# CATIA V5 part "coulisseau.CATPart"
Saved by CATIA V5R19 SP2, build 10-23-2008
Part number: coulisseau
Bounding box of the stored display mesh (mm): x 0 to 20, y -15 to 15, z -15 to 15
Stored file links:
  F:\iaoifma\coulisseau.CATPart
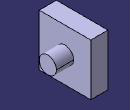
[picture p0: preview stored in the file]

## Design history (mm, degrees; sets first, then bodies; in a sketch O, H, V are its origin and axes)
Body1 (main body)
  Sketch1 on yz-plane, origin (0, 0, 0), H (0, 1, 0), V (0, 0, 1)
    line L1 (-15, 15) -> (15, 15)
    line L2 (15, 15) -> (15, -15)
    line L3 (15, -15) -> (-15, -15)
    line L4 (-15, -15) -> (-15, 15)
    length L2 = 30
    distance L1 H = 15
    length L1 = 30
    distance L2 V = 15
    horizontal: L1 H, L3 H
    vertical: L2 V, L4 V
  Pad1: profile Sketch1, direction (1, 0, 0), length 10
  Sketch2 on end face of Pad1, origin (10, 0, 0), H (0, 1, 0), V (0, 0, 1)
    circle A1 centre (0, 0) radius 5
    radius A1 = 5
  Pad2: profile Sketch2, direction (1, 0, 0), length 10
